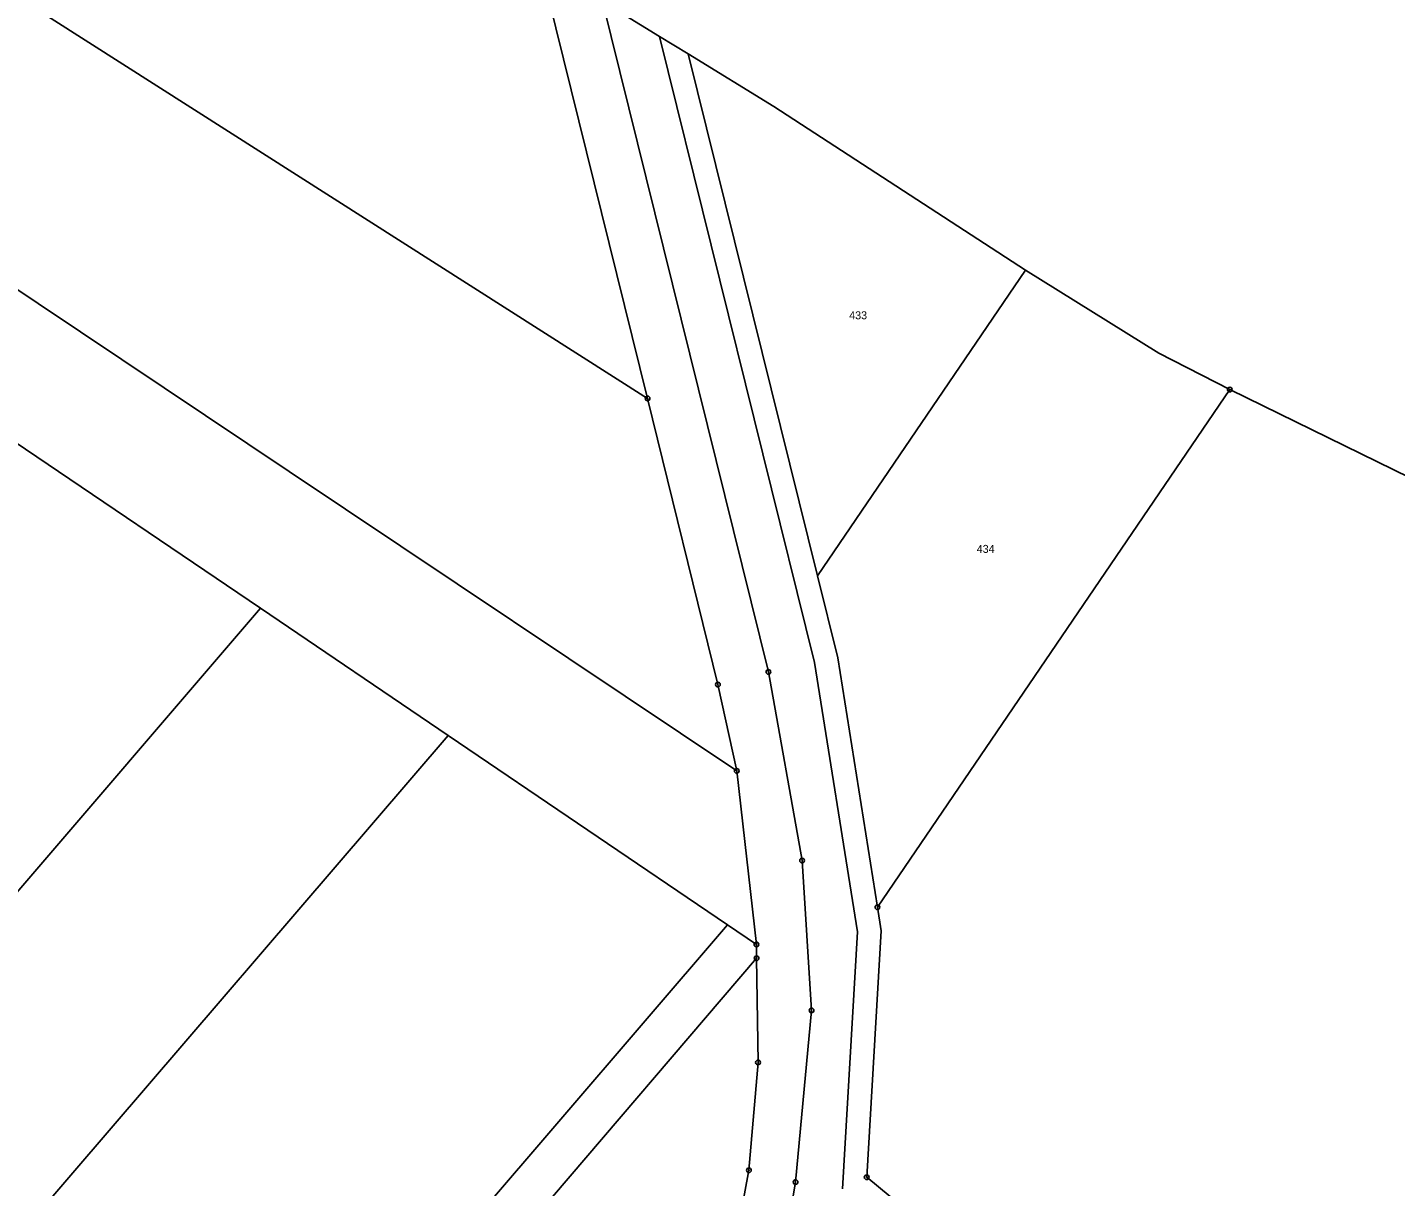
# Model space of a CAD drawing. Extents: x -759947 to -757003, y -1019641 to -1017100.
# Drawn here: x -759255.7 to -758964.9, y -1017584.5 to -1017338.2 of the extents above; entities that cross this region are included whole.
import ezdxf

# ---------------------------------------------------------------- set-up
doc = ezdxf.new("R2010")
doc.units = 0
doc.header["$LTSCALE"] = 0.68
doc.layers.add('1', color=7, linetype='Continuous', lineweight=25)
doc.layers.add('8', color=7, linetype='Continuous', lineweight=25)
doc.layers.add('2', color=7, linetype='Continuous')

msp = doc.modelspace()

# ---------------------------------------------------------------- linework, layer by layer
at = {"layer": '1'}
for p, q in [((-759272.7, -1017322.17), (-759123.87, -1017417.01)), ((-759123.87, -1017417.01), (-759146.57, -1017325.15)), ((-759098.21, -1017475.14), (-759133.48, -1017332.65)), ((-759133.48, -1017332.65), (-759121.31, -1017340.08)), ((-759088.4, -1017473.14), (-759121.31, -1017340.08)), ((-759121.31, -1017340.08), (-759115.22, -1017343.81)), ((-759115.22, -1017343.81), (-759087.79, -1017454.72)), ((-759115.22, -1017343.81), (-759097.03, -1017354.95)), ((-759097.03, -1017354.95), (-759043.56, -1017389.74)), ((-759305.35, -1017362.1), (-759200.02, -1017432.56)), ((-759087.79, -1017454.72), (-759043.56, -1017389.74)), ((-759043.56, -1017389.74), (-759015.24, -1017407.4)), ((-759015.24, -1017407.4), (-759000.16, -1017415.13)), ((-759075.03, -1017525.14), (-759000.16, -1017415.13)), ((-759000.16, -1017415.13), (-758881.51, -1017473.22)), ((-759108.92, -1017477.82), (-759123.87, -1017417.01)), ((-759206.11, -1017461.62), (-759258.44, -1017426.14)), ((-759200.02, -1017432.56), (-759104.92, -1017496.17)), ((-759087.79, -1017454.72), (-759083.48, -1017472.14)), ((-759206.11, -1017461.62), (-759311.14, -1017583.98)), ((-759166.27, -1017488.63), (-759206.11, -1017461.62)), ((-759079.26, -1017530.4), (-759088.4, -1017473.14)), ((-759083.48, -1017472.14), (-759075.03, -1017525.14)), ((-759091.04, -1017515.23), (-759098.21, -1017475.14)), ((-759104.92, -1017496.17), (-759108.92, -1017477.82)), ((-759273.72, -1017613.81), (-759166.27, -1017488.63)), ((-759106.89, -1017528.89), (-759166.27, -1017488.63)), ((-759104.92, -1017496.17), (-759100.74, -1017533.06)), ((-759089.04, -1017547.07), (-759091.04, -1017515.23)), ((-759075.03, -1017525.14), (-759074.23, -1017530.15)), ((-759106.89, -1017528.89), (-759217.86, -1017658.16)), ((-759100.74, -1017533.06), (-759106.89, -1017528.89)), ((-759082.48, -1017584.98), (-759079.26, -1017530.4)), ((-759074.23, -1017530.15), (-759077.32, -1017582.53)), ((-759100.7, -1017535.99), (-759100.74, -1017533.06)), ((-759211.15, -1017665.01), (-759100.7, -1017535.99)), ((-759100.7, -1017535.99), (-759100.41, -1017558.13)), ((-759092.42, -1017583.57), (-759089.04, -1017547.07)), ((-759100.41, -1017558.13), (-759102.33, -1017581.05)), ((-759102.33, -1017581.05), (-759107.59, -1017609.36)), ((-759097.5, -1017613.51), (-759092.42, -1017583.57)), ((-759077.32, -1017582.53), (-758932.25, -1017701.65))]:
    msp.add_line(p, q, dxfattribs=at)
at = {"layer": '8'}
for centre, radius in [((-759000.16, -1017415.1299), 0.5), ((-759000.16, -1017415.1299), 0.0303), ((-759123.87, -1017417.0099), 0.5), ((-759123.87, -1017417.0099), 0.0303), ((-759098.21, -1017475.1399), 0.5), ((-759098.21, -1017475.1399), 0.0303), ((-759108.92, -1017477.8199), 0.5), ((-759108.92, -1017477.8199), 0.0303), ((-759104.92, -1017496.1699), 0.5), ((-759104.92, -1017496.1699), 0.0303), ((-759091.04, -1017515.2299), 0.5), ((-759091.04, -1017515.2299), 0.0303), ((-759075.03, -1017525.1399), 0.5), ((-759075.03, -1017525.1399), 0.0303), ((-759100.74, -1017533.0599), 0.5), ((-759100.74, -1017533.0599), 0.0303), ((-759100.7, -1017535.9899), 0.5), ((-759100.7, -1017535.9899), 0.0303), ((-759089.04, -1017547.0699), 0.5), ((-759089.04, -1017547.0699), 0.0303), ((-759100.41, -1017558.1299), 0.5), ((-759100.41, -1017558.1299), 0.0303), ((-759102.33, -1017581.0499), 0.5), ((-759102.33, -1017581.0499), 0.0303), ((-759092.42, -1017583.5699), 0.5), ((-759092.42, -1017583.5699), 0.0303), ((-759077.32, -1017582.5299), 0.5), ((-759077.32, -1017582.5299), 0.0303)]:
    msp.add_circle(centre, radius, dxfattribs=at)

# ---------------------------------------------------------------- texts
at = {"layer": '2'}
for s, p in [('433', (-759081.03, -1017400.195)), ('434', (-759053.93, -1017449.845))]:
    msp.add_text(s, height=1.7, dxfattribs=at).set_placement(p)

doc.saveas('drawing.dxf')
